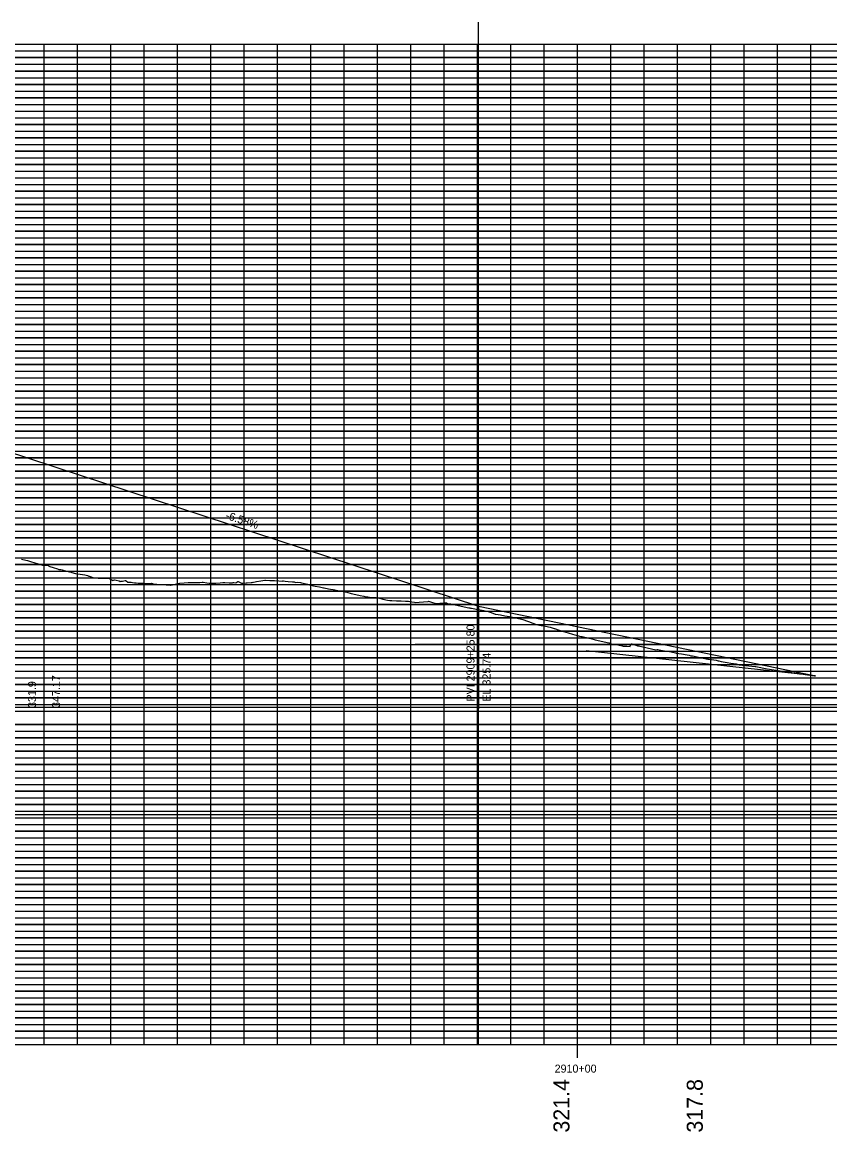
# Model space of a CAD drawing. Extents: x 1195880 to 1289360, y 2059330 to 2086925.
# Drawn here: x 1200977 to 1201583, y 2063535 to 2064367 of the extents above; entities that cross this region are included whole.
import ezdxf

# ---------------------------------------------------------------- set-up
doc = ezdxf.new("R2010")
doc.units = 0
for name, color, linetype in [('41', 7, 'Continuous'), ('43', 7, 'Continuous'), ('Clip', 7, 'Continuous'), ('Default', 7, 'Continuous'), ('Existing Ground PGL', 7, 'Continuous'), ('Grid', 7, 'Continuous'), ('Grid Lables', 7, 'Continuous'), ('Profile', 7, 'Continuous'), ('Profile Annotation', 7, 'Continuous')]:
    doc.layers.add(name, color=color, linetype=linetype)

msp = doc.modelspace()

# ---------------------------------------------------------------- linework, layer by layer
at = {"layer": 'Clip'}
msp.add_lwpolyline([(1200554.29, 2063850.38), (1201658.61, 2063850.38), (1201658.61, 2064200.38), (1200554.29, 2064200.38)], close=True, dxfattribs=at)
at = {"layer": 'Default'}
for p, q in [((1201319.42, 2063600.38), (1201319.42, 2064366.98)), ((1201918.62, 2063900.38), (1201272.04, 2063900.38)), ((1201393.62, 2063600.38), (1201393.62, 2063900.38)), ((1201572.11, 2063876.86), (1201400.1, 2063895.55)), ((1200393.62, 2063600.38), (1201319.42, 2063600.38))]:
    msp.add_line(p, q, dxfattribs=at)
at = {"layer": 'Existing Ground PGL'}
msp.add_lwpolyline([(1200976.66, 2063964.45), (1200980.05, 2063963.56), (1200981.21, 2063963.28), (1200983.43, 2063962.55), (1200986.82, 2063961.5), (1200990.21, 2063960.5), (1200993.12, 2063959.69), (1200993.6, 2063959.69), (1200996.57, 2063959.75), (1200996.99, 2063959.45), (1200997.95, 2063958.78), (1201000.37, 2063958.01), (1201003.76, 2063956.99), (1201004.78, 2063956.7), (1201006.1, 2063956.64), (1201007.15, 2063956.34), (1201010.54, 2063955.43), (1201013.93, 2063954.56), (1201014.53, 2063954.42), (1201017.31, 2063953.72), (1201018.4, 2063953.46), (1201020.7, 2063953.04), (1201022.38, 2063952.75), (1201024.09, 2063952.5), (1201026.17, 2063952.22), (1201027.27, 2063951.68), (1201027.48, 2063951.6), (1201030.87, 2063950.43), (1201031.38, 2063950.27), (1201034.26, 2063950.19), (1201037.64, 2063950.15), (1201038.54, 2063950.16), (1201039.99, 2063950.05), (1201041.03, 2063950.09), (1201041.82, 2063950.13), (1201043.63, 2063949.34), (1201044.42, 2063948.77), (1201045.07, 2063948.32), (1201046.57, 2063948.85), (1201047.81, 2063948.6), (1201049.95, 2063948.21), (1201050.63, 2063947.7), (1201051.2, 2063947.78), (1201052.39, 2063947.98), (1201054.52, 2063948.42), (1201054.58, 2063948.38), (1201054.99, 2063948.1), (1201055.25, 2063948.05), (1201056.41, 2063947.08), (1201057.97, 2063947.11), (1201058.87, 2063947.15), (1201059.87, 2063946.84), (1201061.36, 2063946.63), (1201062.09, 2063946.54), (1201062.62, 2063946.63), (1201064.32, 2063946.46), (1201064.75, 2063946.43), (1201068.14, 2063946.24), (1201071.52, 2063946.12), (1201072.85, 2063946.1), (1201074.28, 2063946.36), (1201074.91, 2063946.12), (1201076.13, 2063945.69), (1201078.3, 2063945.5), (1201081.69, 2063945.26), (1201085.08, 2063945.08), (1201088.46, 2063944.97), (1201088.7, 2063944.96), (1201089.48, 2063944.99), (1201089.96, 2063945.13), (1201091.85, 2063945.51), (1201095.24, 2063946.26), (1201095.39, 2063946.3), (1201098.63, 2063946.51), (1201101.75, 2063946.78), (1201102.02, 2063946.78), (1201105.41, 2063946.81), (1201108.79, 2063946.91), (1201110.46, 2063946.98), (1201112.18, 2063947), (1201113.05, 2063947.02), (1201115.57, 2063946.55), (1201117.32, 2063946.25), (1201118.96, 2063946.28), (1201120.2, 2063946.32), (1201122.35, 2063946.41), (1201125.73, 2063946.6), (1201127.57, 2063946.74), (1201128.87, 2063946.82), (1201129.12, 2063946.8), (1201132.51, 2063946.66), (1201135.01, 2063946.59), (1201135.34, 2063946.84), (1201135.9, 2063946.79), (1201137.48, 2063946.68), (1201138.85, 2063947.7), (1201139.06, 2063947.72), (1201139.29, 2063947.61), (1201141.69, 2063946.44), (1201142.67, 2063946.48), (1201145.29, 2063946.62), (1201146.06, 2063946.67), (1201149.44, 2063946.97), (1201149.45, 2063946.97), (1201149.49, 2063946.99), (1201149.59, 2063946.98), (1201152.84, 2063947.5), (1201156.23, 2063948.11), (1201159.21, 2063948.69), (1201159.62, 2063948.65), (1201163, 2063948.43), (1201166.39, 2063948.27), (1201169.57, 2063948.17), (1201169.78, 2063948.14), (1201172.07, 2063947.88), (1201172.77, 2063948.07), (1201173.17, 2063948), (1201174.41, 2063947.8), (1201176.56, 2063947.61), (1201179.94, 2063947.36), (1201181.15, 2063947.29), (1201182.08, 2063946.93), (1201183.33, 2063947.11), (1201183.37, 2063947.12), (1201185.92, 2063946.84), (1201186.72, 2063946.63), (1201190.11, 2063945.77), (1201191.28, 2063945.5), (1201193.5, 2063944.98), (1201196.88, 2063944.23), (1201200.27, 2063943.54), (1201203.24, 2063942.97), (1201203.66, 2063942.88), (1201207.05, 2063942.15), (1201208.41, 2063941.88), (1201210.44, 2063941.49), (1201213.82, 2063940.88), (1201217.21, 2063940.32), (1201217.83, 2063940.23), (1201220.6, 2063939.49), (1201223.99, 2063938.64), (1201227.38, 2063937.83), (1201230.77, 2063937.07), (1201233.44, 2063936.51), (1201234.15, 2063936.41), (1201236.44, 2063936.12), (1201237.4, 2063935.93), (1201237.54, 2063935.92), (1201237.78, 2063935.89), (1201240.93, 2063935.74), (1201242.74, 2063935.69), (1201244.32, 2063935.29), (1201247.71, 2063934.49), (1201251.09, 2063933.74), (1201252.93, 2063933.36), (1201254.48, 2063933.31), (1201257.87, 2063933.23), (1201260.49, 2063933.2), (1201261.26, 2063933.23), (1201261.4, 2063933.24), (1201264.65, 2063932.96), (1201266.89, 2063932.79), (1201268.03, 2063932.54), (1201269.33, 2063932.28), (1201271.42, 2063932.04), (1201272.38, 2063931.94), (1201274.81, 2063932.12), (1201278.2, 2063932.41), (1201281.59, 2063932.73), (1201282.01, 2063932.78), (1201284.98, 2063931.95), (1201288.03, 2063931.13), (1201288.36, 2063931.16), (1201290.4, 2063931.33), (1201291.75, 2063931.44), (1201293.23, 2063931.56), (1201295.14, 2063931.5), (1201295.33, 2063931.5), (1201296.25, 2063931), (1201297.54, 2063930.95), (1201298.53, 2063930.77), (1201298.95, 2063930.7), (1201300.56, 2063930.42), (1201301.92, 2063930.11), (1201305.3, 2063929.36), (1201308.69, 2063928.63), (1201312.08, 2063927.9), (1201312.41, 2063927.84), (1201312.93, 2063927.76), (1201313.53, 2063927.68), (1201314.25, 2063927.57), (1201315.47, 2063927.33), (1201318.86, 2063926.68), (1201319.52, 2063926.55), (1201321.97, 2063926.24), (1201322.24, 2063926.18), (1201325.63, 2063925.48), (1201325.84, 2063925.44), (1201328.14, 2063924.73), (1201329.02, 2063924.38), (1201332.01, 2063923.2), (1201332.41, 2063923.13), (1201335.8, 2063922.52), (1201339.18, 2063921.9), (1201342.57, 2063921.28), (1201345.96, 2063920.65), (1201347.07, 2063920.44), (1201349.35, 2063919.98), (1201350.66, 2063919.71), (1201352.74, 2063919.04), (1201356.13, 2063917.93), (1201357.63, 2063917.44), (1201359.51, 2063916.72), (1201362.9, 2063915.41), (1201363.83, 2063915.05), (1201366.29, 2063914.68), (1201369.63, 2063914.17), (1201369.68, 2063914.16), (1201373.07, 2063913.27), (1201376.13, 2063912.47), (1201376.45, 2063912.36), (1201379.84, 2063911.17), (1201382.44, 2063910.25), (1201383.23, 2063910.04), (1201386.62, 2063909.11), (1201390.01, 2063908.18), (1201393.39, 2063907.24), (1201396.13, 2063906.48), (1201396.78, 2063906.38), (1201397.15, 2063906.32), (1201400.17, 2063905.58), (1201400.63, 2063905.47), (1201403.56, 2063904.78), (1201406.95, 2063903.97), (1201410.34, 2063903.17), (1201413.72, 2063902.36), (1201417.11, 2063901.56), (1201417.33, 2063901.5), (1201417.66, 2063901.34), (1201418.16, 2063901.22), (1201420.5, 2063900.73), (1201423.89, 2063900.03), (1201427.16, 2063899.33), (1201427.28, 2063899.31), (1201427.98, 2063899.16), (1201428.17, 2063899.14), (1201430.66, 2063899.03), (1201433.06, 2063898.94), (1201433.1, 2063899.08), (1201433.61, 2063900.49), (1201434.05, 2063900.76), (1201434.18, 2063900.84), (1201434.26, 2063900.89), (1201434.31, 2063900.9), (1201434.37, 2063900.89), (1201434.39, 2063900.88), (1201438.25, 2063899.57), (1201438.38, 2063899.53), (1201438.66, 2063899.5), (1201438.83, 2063899.41), (1201439.46, 2063899.34), (1201452.31, 2063896.42), (1201453.36, 2063896.68), (1201453.8, 2063896.54), (1201454.92, 2063896.34), (1201460.27, 2063895.43), (1201461.53, 2063895.26), (1201467.15, 2063894.06), (1201467.24, 2063894.05), (1201467.28, 2063894.06), (1201467.62, 2063893.99), (1201471.57, 2063893.39), (1201475.97, 2063892.63), (1201477.31, 2063892.29), (1201478.68, 2063891.84), (1201479.81, 2063891.78), (1201491.48, 2063889.47), (1201491.66, 2063889.45), (1201491.84, 2063889.44), (1201494.14, 2063889.17), (1201497.73, 2063888.53), (1201499.2, 2063888.18), (1201499.57, 2063888.14), (1201501.43, 2063887.72), (1201505.82, 2063886.99), (1201508.73, 2063886.41), (1201512.63, 2063885.92), (1201514.9, 2063885.08), (1201526.97, 2063883.97), (1201527.39, 2063883.89), (1201527.49, 2063883.88), (1201535.82, 2063882.08), (1201550.68, 2063879.79), (1201552.3, 2063879.54), (1201558.52, 2063878.83), (1201560.19, 2063878.49), (1201562.99, 2063878.01), (1201564.35, 2063877.96), (1201571.4, 2063877), (1201572.11, 2063876.86)], dxfattribs=at)
at = {"layer": 'Grid'}
for p, q in [((1200393.62, 2064350.38), (1201893.62, 2064350.38)), ((1200393.62, 2064350.38), (1201893.62, 2064350.38)), ((1200393.62, 2064345.38), (1201893.62, 2064345.38)), ((1200993.62, 2063600.38), (1200993.62, 2064350.38)), ((1201018.62, 2063600.38), (1201018.62, 2064350.38)), ((1201043.62, 2063600.38), (1201043.62, 2064350.38)), ((1201068.62, 2063600.38), (1201068.62, 2064350.38)), ((1201093.62, 2063600.38), (1201093.62, 2064350.38)), ((1201118.62, 2063600.38), (1201118.62, 2064350.38)), ((1201143.62, 2063600.38), (1201143.62, 2064350.38)), ((1201168.62, 2063600.38), (1201168.62, 2064350.38)), ((1201193.62, 2063600.38), (1201193.62, 2064350.38)), ((1201218.62, 2063600.38), (1201218.62, 2064350.38)), ((1201243.62, 2063600.38), (1201243.62, 2064350.38)), ((1201268.62, 2063600.38), (1201268.62, 2064350.38)), ((1201293.62, 2063600.38), (1201293.62, 2064350.38)), ((1201318.62, 2063600.38), (1201318.62, 2064350.38)), ((1201343.62, 2063600.38), (1201343.62, 2064350.38)), ((1201368.62, 2063600.38), (1201368.62, 2064350.38)), ((1201393.62, 2063600.38), (1201393.62, 2064350.38)), ((1201418.62, 2063600.38), (1201418.62, 2064350.38)), ((1201443.62, 2063600.38), (1201443.62, 2064350.38)), ((1201468.62, 2063600.38), (1201468.62, 2064350.38)), ((1201493.62, 2063600.38), (1201493.62, 2064350.38)), ((1201518.62, 2063600.38), (1201518.62, 2064350.38)), ((1201543.62, 2063600.38), (1201543.62, 2064350.38)), ((1201568.62, 2063600.38), (1201568.62, 2064350.38)), ((1200393.62, 2064340.38), (1201893.62, 2064340.38)), ((1201893.62, 2064340.38), (1200393.62, 2064340.38)), ((1200393.62, 2064335.38), (1201893.62, 2064335.38)), ((1200393.62, 2064330.38), (1201893.62, 2064330.38)), ((1201893.62, 2064330.38), (1200393.62, 2064330.38)), ((1200393.62, 2064325.38), (1201893.62, 2064325.38)), ((1200393.62, 2064320.38), (1201893.62, 2064320.38)), ((1201893.62, 2064320.38), (1200393.62, 2064320.38)), ((1200393.62, 2064315.38), (1201893.62, 2064315.38)), ((1200393.62, 2064310.38), (1201893.62, 2064310.38)), ((1201893.62, 2064310.38), (1200393.62, 2064310.38)), ((1200393.62, 2064305.38), (1201893.62, 2064305.38)), ((1200393.62, 2064300.38), (1201893.62, 2064300.38)), ((1200393.62, 2064295.38), (1201893.62, 2064295.38)), ((1200393.62, 2064290.38), (1201893.62, 2064290.38)), ((1201893.62, 2064290.38), (1200393.62, 2064290.38)), ((1200393.62, 2064285.38), (1201893.62, 2064285.38)), ((1200393.62, 2064280.38), (1201893.62, 2064280.38)), ((1201893.62, 2064280.38), (1200393.62, 2064280.38)), ((1200393.62, 2064275.38), (1201893.62, 2064275.38)), ((1200393.62, 2064270.38), (1201893.62, 2064270.38)), ((1201893.62, 2064270.38), (1200393.62, 2064270.38)), ((1200393.62, 2064265.38), (1201893.62, 2064265.38)), ((1200393.62, 2064260.38), (1201893.62, 2064260.38)), ((1201893.62, 2064260.38), (1200393.62, 2064260.38)), ((1200393.62, 2064255.38), (1201893.62, 2064255.38)), ((1200393.62, 2064250.38), (1201893.62, 2064250.38)), ((1200393.62, 2064245.38), (1201893.62, 2064245.38)), ((1200393.62, 2064240.38), (1201893.62, 2064240.38)), ((1201893.62, 2064240.38), (1200393.62, 2064240.38)), ((1200393.62, 2064235.38), (1201893.62, 2064235.38)), ((1200393.62, 2064230.38), (1201893.62, 2064230.38)), ((1201893.62, 2064230.38), (1200393.62, 2064230.38)), ((1200393.62, 2064225.38), (1201893.62, 2064225.38)), ((1200393.62, 2064220.38), (1201893.62, 2064220.38)), ((1201893.62, 2064220.38), (1200393.62, 2064220.38)), ((1200393.62, 2064215.38), (1201893.62, 2064215.38)), ((1200393.62, 2064210.38), (1201893.62, 2064210.38)), ((1201893.62, 2064210.38), (1200393.62, 2064210.38)), ((1200393.62, 2064205.38), (1201893.62, 2064205.38)), ((1200393.62, 2064200.38), (1201893.62, 2064200.38)), ((1200393.62, 2064195.38), (1201893.62, 2064195.38)), ((1200393.62, 2064190.38), (1201893.62, 2064190.38)), ((1201893.62, 2064190.38), (1200393.62, 2064190.38)), ((1200393.62, 2064185.38), (1201893.62, 2064185.38)), ((1200393.62, 2064180.38), (1201893.62, 2064180.38)), ((1201893.62, 2064180.38), (1200393.62, 2064180.38)), ((1200393.62, 2064175.38), (1201893.62, 2064175.38)), ((1200393.62, 2064170.38), (1201893.62, 2064170.38)), ((1201893.62, 2064170.38), (1200393.62, 2064170.38)), ((1200393.62, 2064165.38), (1201893.62, 2064165.38)), ((1200393.62, 2064160.38), (1201893.62, 2064160.38)), ((1201893.62, 2064160.38), (1200393.62, 2064160.38)), ((1200393.62, 2064155.38), (1201893.62, 2064155.38)), ((1200393.62, 2064150.38), (1201893.62, 2064150.38)), ((1200393.62, 2064145.38), (1201893.62, 2064145.38)), ((1200393.62, 2064140.38), (1201893.62, 2064140.38)), ((1201893.62, 2064140.38), (1200393.62, 2064140.38)), ((1200393.62, 2064135.38), (1201893.62, 2064135.38)), ((1200393.62, 2064130.38), (1201893.62, 2064130.38)), ((1201893.62, 2064130.38), (1200393.62, 2064130.38)), ((1200393.62, 2064125.38), (1201893.62, 2064125.38)), ((1200393.62, 2064120.38), (1201893.62, 2064120.38)), ((1201893.62, 2064120.38), (1200393.62, 2064120.38)), ((1200393.62, 2064115.38), (1201893.62, 2064115.38)), ((1200393.62, 2064110.38), (1201893.62, 2064110.38)), ((1201893.62, 2064110.38), (1200393.62, 2064110.38)), ((1200393.62, 2064105.38), (1201893.62, 2064105.38)), ((1200393.62, 2064100.38), (1201893.62, 2064100.38)), ((1200393.62, 2064095.38), (1201893.62, 2064095.38)), ((1200393.62, 2064090.38), (1201893.62, 2064090.38)), ((1201893.62, 2064090.38), (1200393.62, 2064090.38)), ((1200393.62, 2064085.38), (1201893.62, 2064085.38)), ((1200393.62, 2064080.38), (1201893.62, 2064080.38)), ((1201893.62, 2064080.38), (1200393.62, 2064080.38)), ((1200393.62, 2064075.38), (1201893.62, 2064075.38)), ((1200393.62, 2064070.38), (1201893.62, 2064070.38)), ((1201893.62, 2064070.38), (1200393.62, 2064070.38)), ((1200393.62, 2064065.38), (1201893.62, 2064065.38)), ((1200393.62, 2064060.38), (1201893.62, 2064060.38)), ((1201893.62, 2064060.38), (1200393.62, 2064060.38)), ((1200393.62, 2064055.38), (1201893.62, 2064055.38)), ((1200393.62, 2064050.38), (1201893.62, 2064050.38)), ((1200393.62, 2064045.38), (1201893.62, 2064045.38)), ((1200393.62, 2064040.38), (1201893.62, 2064040.38)), ((1201893.62, 2064040.38), (1200393.62, 2064040.38)), ((1200393.62, 2064035.38), (1201893.62, 2064035.38)), ((1200393.62, 2064030.38), (1201893.62, 2064030.38)), ((1201893.62, 2064030.38), (1200393.62, 2064030.38)), ((1200393.62, 2064025.38), (1201893.62, 2064025.38)), ((1200393.62, 2064020.38), (1201893.62, 2064020.38)), ((1201893.62, 2064020.38), (1200393.62, 2064020.38)), ((1200393.62, 2064015.38), (1201893.62, 2064015.38)), ((1200393.62, 2064010.38), (1201893.62, 2064010.38)), ((1201893.62, 2064010.38), (1200393.62, 2064010.38)), ((1200393.62, 2064005.38), (1201893.62, 2064005.38)), ((1200393.62, 2064000.38), (1201893.62, 2064000.38)), ((1200393.62, 2063995.38), (1201893.62, 2063995.38)), ((1200393.62, 2063990.38), (1201893.62, 2063990.38)), ((1201893.62, 2063990.38), (1200393.62, 2063990.38)), ((1200393.62, 2063985.38), (1201893.62, 2063985.38)), ((1201893.62, 2063980.44), (1200393.62, 2063980.44)), ((1200393.62, 2063980.38), (1201893.62, 2063980.38)), ((1201893.62, 2063980.38), (1200393.62, 2063980.38)), ((1200393.62, 2063975.38), (1201893.62, 2063975.38)), ((1200393.62, 2063970.38), (1201893.62, 2063970.38)), ((1201893.62, 2063970.38), (1200393.62, 2063970.38)), ((1200393.62, 2063965.38), (1201893.62, 2063965.38)), ((1200393.62, 2063960.38), (1201893.62, 2063960.38)), ((1201893.62, 2063960.38), (1200393.62, 2063960.38)), ((1200393.62, 2063955.38), (1201893.62, 2063955.38)), ((1200393.62, 2063950.38), (1201893.62, 2063950.38)), ((1200393.62, 2063945.38), (1201893.62, 2063945.38)), ((1200393.62, 2063940.38), (1201893.62, 2063940.38)), ((1201893.62, 2063940.38), (1200393.62, 2063940.38)), ((1200393.62, 2063935.38), (1201893.62, 2063935.38)), ((1200393.62, 2063930.38), (1201893.62, 2063930.38)), ((1201893.62, 2063930.38), (1200393.62, 2063930.38)), ((1200393.62, 2063925.38), (1201893.62, 2063925.38)), ((1200393.62, 2063920.38), (1201893.62, 2063920.38)), ((1201893.62, 2063920.38), (1200393.62, 2063920.38)), ((1200393.62, 2063915.38), (1201893.62, 2063915.38)), ((1200393.62, 2063910.38), (1201893.62, 2063910.38)), ((1201893.62, 2063910.38), (1200393.62, 2063910.38)), ((1200393.62, 2063905.38), (1201893.62, 2063905.38)), ((1200393.62, 2063900.38), (1201893.62, 2063900.38)), ((1200393.62, 2063895.38), (1201893.62, 2063895.38)), ((1200393.62, 2063890.38), (1201893.62, 2063890.38)), ((1201893.62, 2063890.38), (1200393.62, 2063890.38)), ((1200393.62, 2063885.38), (1201893.62, 2063885.38)), ((1200393.62, 2063880.38), (1201893.62, 2063880.38)), ((1200393.62, 2063875.38), (1201893.62, 2063875.38)), ((1200393.62, 2063870.38), (1201893.62, 2063870.38)), ((1201893.62, 2063870.38), (1200393.62, 2063870.38)), ((1200393.62, 2063865.38), (1201893.62, 2063865.38)), ((1200393.62, 2063860.38), (1201893.62, 2063860.38)), ((1201893.62, 2063860.38), (1200393.62, 2063860.38)), ((1200393.62, 2063855.38), (1201893.62, 2063855.38)), ((1200393.62, 2063853.5), (1201893.62, 2063853.5)), ((1200393.62, 2063850.38), (1201893.62, 2063850.38)), ((1200393.62, 2063840.38), (1201893.62, 2063840.38)), ((1201893.62, 2063840.38), (1200393.62, 2063840.38)), ((1200393.62, 2063835.38), (1201893.62, 2063835.38)), ((1200393.62, 2063830.38), (1201893.62, 2063830.38)), ((1201893.62, 2063830.38), (1200393.62, 2063830.38)), ((1200393.62, 2063825.38), (1201893.62, 2063825.38)), ((1200393.62, 2063820.38), (1201893.62, 2063820.38)), ((1201893.62, 2063820.38), (1200393.62, 2063820.38)), ((1200393.62, 2063815.38), (1201893.62, 2063815.38)), ((1200393.62, 2063810.38), (1201893.62, 2063810.38)), ((1201893.62, 2063810.38), (1200393.62, 2063810.38)), ((1200393.62, 2063805.38), (1201893.62, 2063805.38)), ((1200393.62, 2063800.38), (1201893.62, 2063800.38)), ((1200393.62, 2063795.38), (1201893.62, 2063795.38)), ((1200393.62, 2063790.38), (1201893.62, 2063790.38)), ((1201893.62, 2063790.38), (1200393.62, 2063790.38)), ((1200393.62, 2063785.38), (1201893.62, 2063785.38)), ((1200393.62, 2063780.38), (1201893.62, 2063780.38)), ((1201893.62, 2063780.38), (1200393.62, 2063780.38)), ((1200393.62, 2063775.38), (1201893.62, 2063775.38)), ((1201893.62, 2063772.78), (1200393.62, 2063772.78)), ((1200393.62, 2063770.38), (1201893.62, 2063770.38)), ((1200393.62, 2063765.38), (1201893.62, 2063765.38)), ((1200393.62, 2063760.38), (1201893.62, 2063760.38)), ((1201893.62, 2063760.38), (1200393.62, 2063760.38)), ((1200393.62, 2063755.38), (1201893.62, 2063755.38)), ((1200393.62, 2063750.38), (1201893.62, 2063750.38)), ((1200393.62, 2063745.38), (1201893.62, 2063745.38)), ((1200393.62, 2063740.38), (1201893.62, 2063740.38)), ((1201893.62, 2063740.38), (1200393.62, 2063740.38)), ((1200393.62, 2063735.38), (1201893.62, 2063735.38)), ((1200393.62, 2063730.38), (1201893.62, 2063730.38)), ((1201893.62, 2063730.38), (1200393.62, 2063730.38)), ((1200393.62, 2063725.38), (1201893.62, 2063725.38)), ((1200393.62, 2063720.38), (1201893.62, 2063720.38)), ((1201893.62, 2063720.38), (1200393.62, 2063720.38)), ((1200393.62, 2063715.38), (1201893.62, 2063715.38)), ((1200393.62, 2063710.38), (1201893.62, 2063710.38)), ((1201893.62, 2063710.38), (1200393.62, 2063710.38)), ((1200393.62, 2063705.38), (1201893.62, 2063705.38)), ((1200393.62, 2063700.38), (1201893.62, 2063700.38)), ((1200393.62, 2063695.38), (1201893.62, 2063695.38)), ((1200393.62, 2063690.38), (1201893.62, 2063690.38)), ((1201893.62, 2063690.38), (1200393.62, 2063690.38)), ((1200393.62, 2063685.38), (1201893.62, 2063685.38)), ((1200393.62, 2063680.38), (1201893.62, 2063680.38)), ((1201893.62, 2063680.38), (1200393.62, 2063680.38)), ((1200393.62, 2063675.38), (1201893.62, 2063675.38)), ((1200393.62, 2063670.38), (1201893.62, 2063670.38)), ((1201893.62, 2063670.38), (1200393.62, 2063670.38)), ((1200393.62, 2063665.38), (1201893.62, 2063665.38)), ((1200393.62, 2063660.38), (1201893.62, 2063660.38)), ((1201893.62, 2063660.38), (1200393.62, 2063660.38)), ((1200393.62, 2063655.38), (1201893.62, 2063655.38)), ((1200393.62, 2063650.38), (1201893.62, 2063650.38)), ((1200393.62, 2063645.38), (1201893.62, 2063645.38)), ((1200393.62, 2063640.38), (1201893.62, 2063640.38)), ((1201893.62, 2063640.38), (1200393.62, 2063640.38)), ((1200393.62, 2063635.38), (1201893.62, 2063635.38)), ((1200393.62, 2063630.38), (1201893.62, 2063630.38)), ((1201893.62, 2063630.38), (1200393.62, 2063630.38)), ((1200393.62, 2063625.38), (1201893.62, 2063625.38)), ((1200393.62, 2063620.38), (1201893.62, 2063620.38)), ((1201893.62, 2063620.38), (1200393.62, 2063620.38)), ((1200393.62, 2063615.38), (1201893.62, 2063615.38)), ((1200393.62, 2063610.38), (1201893.62, 2063610.38)), ((1201893.62, 2063610.38), (1200393.62, 2063610.38)), ((1200393.62, 2063605.38), (1201893.62, 2063605.38)), ((1200993.62, 2063600.38), (1200993.62, 2063603.38)), ((1201018.62, 2063600.38), (1201018.62, 2063603.38)), ((1201043.62, 2063600.38), (1201043.62, 2063603.38)), ((1201068.62, 2063600.38), (1201068.62, 2063603.38)), ((1201093.62, 2063600.38), (1201093.62, 2063603.38)), ((1201118.62, 2063600.38), (1201118.62, 2063603.38)), ((1201143.62, 2063600.38), (1201143.62, 2063603.38)), ((1201168.62, 2063600.38), (1201168.62, 2063603.38)), ((1201193.62, 2063600.38), (1201193.62, 2063603.38)), ((1201218.62, 2063600.38), (1201218.62, 2063603.38)), ((1201243.62, 2063600.38), (1201243.62, 2063603.38)), ((1201268.62, 2063600.38), (1201268.62, 2063603.38)), ((1201293.62, 2063600.38), (1201293.62, 2063603.38)), ((1201318.62, 2063600.38), (1201318.62, 2063603.38)), ((1201343.62, 2063600.38), (1201343.62, 2063603.38)), ((1201368.62, 2063600.38), (1201368.62, 2063603.38)), ((1201418.62, 2063600.38), (1201418.62, 2063603.38)), ((1201443.62, 2063600.38), (1201443.62, 2063603.38)), ((1201468.62, 2063600.38), (1201468.62, 2063603.38)), ((1201493.62, 2063600.38), (1201493.62, 2063603.38)), ((1201518.62, 2063600.38), (1201518.62, 2063603.38)), ((1201543.62, 2063600.38), (1201543.62, 2063603.38)), ((1201568.62, 2063600.38), (1201568.62, 2063603.38)), ((1200393.62, 2063600.38), (1201893.62, 2063600.38)), ((1201393.62, 2063590.38), (1201393.62, 2063600.38))]:
    msp.add_line(p, q, dxfattribs=at)
at = {"layer": 'Profile'}
for p, q in [((1200963.83, 2064046.02), (1201319.42, 2063929.08)), ((1201319.42, 2063929.08), (1201572.11, 2063876.86))]:
    msp.add_line(p, q, dxfattribs=at)
at = {"layer": 'Profile Annotation'}
msp.add_line((1201319.42, 2063929.08), (1201319.42, 2063852.21), dxfattribs=at)

# ---------------------------------------------------------------- texts
at = {"layer": '41'}
for s, height, p in [('331.9', 6, (1200987.62, 2063852.78)), ('321.4', 12, (1201387.62, 2063534.38)), ('317.8', 12, (1201487.62, 2063534.38))]:
    msp.add_text(s, height=height, rotation=90, dxfattribs=at).set_placement(p)
at = {"layer": '43'}
msp.add_text('347.17', height=6, rotation=90, dxfattribs=at).set_placement((1201005.62, 2063852.78))
at = {"layer": 'Grid Lables'}
msp.add_text('2910+00', height=6, dxfattribs=at).set_placement((1201376.5, 2063579.38))
at = {"layer": 'Profile Annotation'}
for s, rotation, p in [('-6.58%', 341.79718, (1201129.17, 2063994.81)), ('PVI 2909+25.80', 90, (1201316.42, 2063857.57)), ('EL 325.74', 90, (1201328.42, 2063857.57))]:
    msp.add_text(s, height=6, rotation=rotation, dxfattribs=at).set_placement(p)

doc.saveas('drawing.dxf')
